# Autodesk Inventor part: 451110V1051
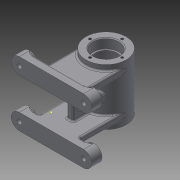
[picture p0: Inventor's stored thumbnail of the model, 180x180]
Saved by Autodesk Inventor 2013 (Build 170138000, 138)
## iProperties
Created: 2015-11
Part Number: 451110V1051
Material: 일반
Document SubType Name: Modeling
Designer: Administrator
Density: 1 g/cm^3
Author: Administrator
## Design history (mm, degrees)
sketch "스케치1"
  geometry: C1 r 25 at (0, 0); 1 further point
  constraints: 1 centre point, 1 coincident
  dimensions: "d0" = 50 diameter of C1
extrude "돌출1" new body sketch "스케치1" stored distance "d1" = 70; taper "d2" = 0 deg
sketch "스케치2"
  geometry: C1 r 25 at (0, 0) reference; C2 r 16 at (0, 0)
  constraints: 1 centre point, 1 coincident
  dimensions: "d3" = 32 diameter of C2
extrude "돌출2" cut sketch "스케치2" distance "d4" = 12; taper "d5" = 0 deg
sketch "스케치3"
  geometry: C1 r 16 at (0, 0) reference; C2 r 14 at (0, 0)
  constraints: 1 centre point, 1 coincident
  dimensions: "d6" = 28 diameter of C2
extrude "돌출3" cut sketch "스케치3" distance "d7" = 2; taper "d8" = 0 deg
sketch "스케치4"
  geometry: C1 r 14 at (0, 0) reference; C2 r 21 at (0, 0)
  constraints: 1 centre point, 1 coincident
  dimensions: "d9" = 42 diameter of C2
extrude "돌출4" cut sketch "스케치4" distance "d10" = 42; taper "d11" = 0 deg
node "작업 평면1"
sketch "스케치5"
  geometry: C1 r 5 at (0, 0); 1 further point
  constraints: 1 centre point, 1 coincident
  dimensions: "d13" = 10 diameter of C1
extrude "돌출5" join sketch "스케치5" stored distance "d14" = 42; taper "d15" = 0 deg
sketch "스케치6"
  geometry: C1 r 5 at (0, 0) reference
hole "구멍1" sketch "스케치6" at (0, 0) diameter "d16" = 5.188; stored, may be unused: countersink angle "d20" = 90 deg, drill point angle "d22" = 118 deg; dims "d17" = 20, "d18" = 4, "d19" = 2, "d21" = 20
sketch "스케치7"
  geometry: L1 (0, 0)-(14, -24.249); L2 (0, 0)-(0, -37.188)
  constraints: 4 end point, 1 vertical
  dimensions: "d23" = 28 distance of L1.start L1.end; "d24" = 30 deg angle of L1 L2
node "작업 평면2"
sketch "스케치8"
  geometry: C1 r 6 at (0, 0); 1 further point
  constraints: 1 centre point, 1 coincident
  dimensions: "d25" = 12 diameter of C1
extrude "돌출6" join sketch "스케치8" stored distance "d26" = 42; taper "d27" = 0 deg
sketch "스케치9"
  geometry: C1 r 6 at (0, 0) reference
hole "구멍2" sketch "스케치9" at (0, 0) diameter "d28" = 5.188; stored, may be unused: countersink angle "d32" = 90 deg, drill point angle "d34" = 118 deg; dims "d29" = 20, "d30" = 4, "d31" = 2, "d33" = 20
node "작업 평면3"
sketch "스케치10"
  geometry: 1 further point
sketch "스케치11"
  geometry: L1 (40, 40)-(-40, 40); L2 (-40, 40)-(-40, -40); L3 (-40, -40)-(40, -40); L4 (40, -40)-(40, 40); L5 (40, 40)-(-40, -40); L6 (-40, 40)-(40, -40); L7 (0, 0)-(0, -20); L8 (0, -20)-(40, -20); L9 (0, -20)-(-40, -20); L10 (0, 0)-(0, 20); L11 (0, 20)-(40, 20); L12 (0, 20)-(-40, 20)
  constraints: 24 end point, 6 perpendicular, 4 point on line, 3 parallel, 2 midpoint, 1 horizontal
  dimensions: "d36" = 80 distance of L3.end L2.end; "d37" = 80 distance of L2.end L1.end; "d38" = 20 distance of L7.start L7.end; "d39" = 20 distance of L7.start L10.end
extrude "돌출7" join sketch "스케치11" distance "d40" = 10; taper "d41" = 0 deg
sketch "스케치12"
  geometry: L1 (40, -40)-(40, -20) reference; L2 (-40, -20)-(-40, -40) reference; L3 (40, 40)-(-40, 40) reference; L4 (40, 20)-(40, 40) reference; L5 (-40, 20)-(40, 20) reference; L6 (-40, 40)-(-40, 20) reference; C1 r 10 at (-40, -30); C2 r 10 at (40, -30); C3 r 10 at (-40, 30); C4 r 10 at (40, 30); 1 further point
  constraints: 4 centre point, 4 midpoint
  dimensions: "d42" = 20 diameter of C1; "d43" = 20 diameter of C2; "d44" = 20 diameter of C3; "d45" = 20 diameter of C4
extrude "돌출8" join sketch "스케치12" distance "d46" = 3; taper "d48" = 0 deg; dims "d47" = 10, "d49" = 0
sketch "스케치13"
  geometry: L1 (40, -20)-(-40, -20) reference; L2 (0, 0)-(0, -20); L3 (0, -20)-(0, -24); L4 (-25, -28)-(25, -28); L5 (25, -28)-(25, -20); L6 (25, -20)-(-25, -20); L7 (-25, -20)-(-25, -28); L8 (-25, -28)-(25, -20); L9 (25, -28)-(-25, -20)
  constraints: 16 end point, 3 midpoint, 2 parallel, 1 collinear, 1 horizontal, 1 perpendicular
  dimensions: "d50" = 20 distance of L2.start L2.end; "d52" = 4 distance of L2.end L3.end; "d53" = 50 distance of L6.end L5.end; "d54" = 8 distance of L5.end L4.end
extrude "돌출9" join sketch "스케치13" stored distance "d55" = 3; taper "d56" = 0 deg
sketch "스케치14"
  geometry: C1 r 10 at (0, 0) reference; C2 r 10 at (0, 60) reference; C3 r 10 at (80, 60) reference; C4 r 10 at (80, 0) reference; 1 further point
hole "구멍3" sketch "스케치14" at (0, 60), (0, 0), (80, 0), (80, 60) diameter "d57" = 6; stored, may be unused: countersink angle "d61" = 90 deg, drill point angle "d63" = 118 deg; dims "d58" = 6, "d59" = 12, "d60" = 4, "d62" = 20
chamfer "모따기1" distance "d64" = 1; stored, may be unused: second distance "d65" = 2, angle "d66" = 45 deg
sketch "스케치15" dims "d67" = 40
  geometry: L1 (0, 0)-(0, 20); C1 r 25 at (0, 0) reference
  constraints: 2 end point, 1 coincident, 1 vertical, 1 vertical alignment, 2 other
hole "구멍4" sketch "스케치15" at (0, 20) diameter "d68" = 3.242; stored, may be unused: countersink angle "d72" = 90 deg, drill point angle "d74" = 118 deg; dims "d69" = 8, "d70" = 12, "d71" = 4, "d73" = 10
sketch "스케치16" dims "d31" = 2, "d78" = 40
  geometry: L1 (0, 0)-(0, 20); C1 r 25 at (0, 0) reference
  constraints: 2 end point, 1 coincident, 1 vertical, 1 vertical alignment, 2 other
hole "구멍5" sketch "스케치16" at (0, 20) diameter "d79" = 3.242; stored, may be unused: countersink angle "d83" = 90 deg, drill point angle "d85" = 118 deg; dims "d80" = 8, "d81" = 12, "d82" = 4, "d84" = 10
sketch "스케치17"
  geometry: L1 (0, 0)-(-25, 0); L2 (-25, 0)-(-35, 0); L3 (-45, -20)-(-25, -20); L4 (-25, -20)-(-25, 20); L5 (-25, 20)-(-45, 20); L6 (-45, 20)-(-45, -20); L7 (-45, -20)-(-25, 20); L8 (-25, -20)-(-45, 20); L9 (-25, 20)-(-23, 20); L10 (-23, 20)-(-23, -20); L11 (-23, -20)-(-25, -20)
  constraints: 22 end point, 3 perpendicular, 2 horizontal, 2 midpoint, 2 parallel, 1 collinear
  dimensions: "d89" = 25 distance of L1.start L1.end; "d90" = 10 distance of L1.end L2.end; "d91" = 20 distance of L5.end L4.end; "d92" = 40 distance of L4.end L3.end
extrude "돌출10" join sketch "스케치17" stored distance "d93" = 8; taper "d94" = 0 deg
sketch "스케치18"
  geometry: L1 (20, -25)-(-20, -25) reference; L2 (-20, -45)-(20, -45) reference; L3 (0, -25)-(0, -35); L4 (8, -38.5)-(-8, -38.5); L5 (-11.5, -35)-(-11.5, -35); L6 (-8, -31.5)-(8, -31.5); L7 (11.5, -35)-(11.5, -35); L8 (11.5, -38.5)-(-11.5, -31.5); L9 (-11.5, -38.5)-(11.5, -31.5); A1 r 3.5 centre (-8, -35) between (-8, -31.5) and (-11.5, -35); A2 r 3.5 centre (-8, -35) between (-11.5, -35) and (-8, -38.5); A3 r 3.5 centre (8, -35) between (11.5, -35) and (8, -31.5); A4 r 3.5 centre (8, -35) between (8, -38.5) and (11.5, -35); 1 further point
  constraints: 14 end point, 8 point on circle, 8 point on line, 8 tangent, 4 centre point, 3 equal radius, 3 midpoint, 2 parallel, 2 perpendicular, 1 horizontal
  dimensions: "d95" = 10 distance of L3.start L3.end; "d96" = 23 distance of L8.end L9.end; "d97" = 7 distance of L9.start L8.end; "d98" = 3.5 radius of A1
extrude "돌출11" cut sketch "스케치18" distance "d99" = 8; taper "d100" = 0 deg
node "작업 평면4"
sketch "스케치19"
  geometry: L1 (-25, -35)-(25, -35) reference; L2 (-25, -35)-(-25, 35) reference; L3 (0, -28)-(0, -20) reference; 2 further points
  constraints: 1 other
  dimensions: "d102" = 35 distance from line of L1 point (0, 0); "d104" = 25 distance from line of L2 point (0, 0)
feature "엠보싱1" sketch "스케치19" dims "d105" = 0.5, "d106" = 0
extrude "돌출12" join sketch "스케치17" stored distance "d107" = 8; taper "d108" = 0 deg
fillet "모깎기1" dims "d109" = 2
fillet "모깎기2" dims "d110" = 2
fillet "모깎기3" dims "d111" = 2, "d112" = 2
fillet "모깎기4" dims "d113" = 2, "d114" = 2
fillet "모깎기5" dims "d115" = 2
fillet "모깎기6" dims "d116" = 2
fillet "모깎기7" dims "d117" = 2
fillet "모깎기8" dims "d118" = 2, "d119" = 3
fillet "모깎기9" dims "d120" = 0.3
chamfer "모따기2" distance "d121" = 1; stored, may be unused: second distance "d122" = 2, angle "d123" = 45 deg
node "솔리드1"
mirror "대칭1"
mirror "대칭2"
pattern_circular "원형 패턴1" dims angle "d76" = 360 deg
pattern_circular "원형 패턴2" dims angle "d87" = 360 deg
node "투영된 루프1"
node "투영된 루프2"
node "투영된 루프3"
other parameters: "d12" = 28, "d35" = -68, "d101" = -25
